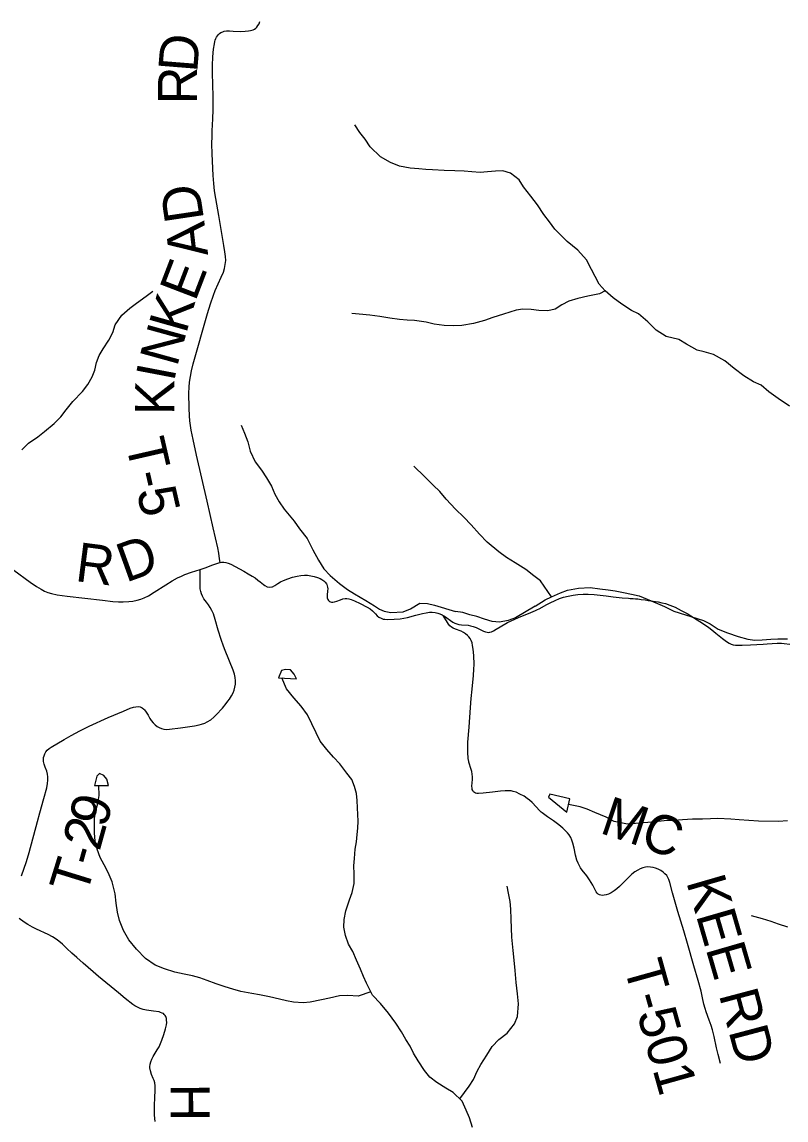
# Model space of a CAD drawing. Extents: x 0 to 34, y 0 to 22.
# Drawn here: x 7.268 to 8.379, y 17.022 to 18.618 of the extents above; entities that cross this region are included whole.
import ezdxf

# ---------------------------------------------------------------- set-up
doc = ezdxf.new("R2010")
doc.units = 0
for name, color, linetype in [('GM_X_County_Road', 7, 'Continuous'), ('GM_X_County_Road_Text', 7, 'Continuous'), ('GM_X_Minor_Lake', 7, 'Continuous'), ('GM_X_Minor_River', 7, 'Continuous'), ('GM_X_Township_Road', 7, 'Continuous'), ('GM_X_Township_Road_Text', 7, 'Continuous')]:
    doc.layers.add(name, color=color, linetype=linetype)

msp = doc.modelspace()

# ---------------------------------------------------------------- linework, layer by layer
at = {"layer": 'GM_X_County_Road'}
for points in [[(7.5272, 17.8224), (7.5359, 17.8253), (7.5444, 17.8284), (7.5514, 17.8311), (7.5545, 17.832), (7.5563, 17.8323)], [(7.5563, 17.8323), (7.5583, 17.8326), (7.5616, 17.8326), (7.5648, 17.8322), (7.5679, 17.8314), (7.572, 17.8297), (7.5781, 17.8265), (7.5906, 17.8196), (7.5971, 17.816), (7.6031, 17.8127), (7.6073, 17.8099), (7.6113, 17.8069), (7.6147, 17.8041), (7.6195, 17.8002), (7.6214, 17.7988), (7.6246, 17.7972), (7.628, 17.7965), (7.6313, 17.797), (7.6323, 17.7972), (7.6361, 17.7991), (7.6402, 17.8018), (7.644, 17.8041), (7.6485, 17.8063), (7.6549, 17.8088), (7.6615, 17.8109), (7.6682, 17.8126), (7.6738, 17.8135), (7.6788, 17.8138), (7.6832, 17.8137), (7.6883, 17.8132), (7.6932, 17.8122), (7.6981, 17.8107), (7.7016, 17.8092), (7.7044, 17.8076), (7.7071, 17.8057), (7.7089, 17.804), (7.7108, 17.8014), (7.7115, 17.8003), (7.7126, 17.7965), (7.7128, 17.7939), (7.7126, 17.7913), (7.7117, 17.7851), (7.7118, 17.7827), (7.712, 17.781), (7.7129, 17.7784), (7.7139, 17.7771), (7.7151, 17.7759), (7.717, 17.775), (7.7181, 17.7747), (7.7203, 17.7746), (7.7226, 17.7751), (7.7259, 17.7763), (7.7312, 17.7783), (7.7349, 17.7794), (7.7381, 17.7799), (7.7407, 17.7799), (7.7432, 17.7795), (7.7469, 17.7785), (7.7516, 17.7766), (7.7601, 17.7726), (7.7701, 17.7674), (7.7744, 17.7648), (7.7778, 17.762), (7.7822, 17.7575), (7.7848, 17.7549), (7.7871, 17.753), (7.7902, 17.7512), (7.7935, 17.7501), (7.7958, 17.7498), (7.8, 17.7496), (7.8093, 17.7499), (7.8179, 17.7506), (7.8234, 17.7514), (7.8288, 17.7525), (7.8407, 17.7558), (7.8503, 17.7583), (7.8558, 17.7594), (7.8608, 17.76), (7.8645, 17.76), (7.8689, 17.7597), (7.8725, 17.7588), (7.8755, 17.7578), (7.8788, 17.7563), (7.8804, 17.7553)], [(7.2568, 17.821), (7.2804, 17.8039), (7.2896, 17.7977), (7.2964, 17.7936), (7.3013, 17.7909), (7.3063, 17.7888), (7.3116, 17.7872), (7.3194, 17.7855), (7.334, 17.7833), (7.3856, 17.7774), (7.4003, 17.7757), (7.4089, 17.7751), (7.4157, 17.775), (7.4237, 17.7756), (7.4298, 17.7763), (7.4358, 17.7775), (7.4411, 17.779), (7.4462, 17.7809), (7.4523, 17.7838), (7.4607, 17.789), (7.4773, 17.7998), (7.4869, 17.8056), (7.4945, 17.8099), (7.5001, 17.8127), (7.5052, 17.8149), (7.5146, 17.8182), (7.5272, 17.8224)], [(7.8804, 17.7553), (7.8825, 17.7541), (7.8945, 17.7457), (7.8976, 17.7441), (7.9003, 17.743), (7.9032, 17.7423), (7.9073, 17.7417), (7.9167, 17.7411), (7.9204, 17.7405), (7.9241, 17.7395), (7.9282, 17.738), (7.9333, 17.7356), (7.9393, 17.7325), (7.9421, 17.7314), (7.9444, 17.7309), (7.9467, 17.7307), (7.9484, 17.7309), (7.9506, 17.7315), (7.9534, 17.7328), (7.9576, 17.7352), (7.9633, 17.7388), (7.9741, 17.7449), (7.9791, 17.7475), (7.9836, 17.7495), (7.9899, 17.7523), (8.0077, 17.7595), (8.0144, 17.7626), (8.0173, 17.7638), (8.02, 17.7652), (8.0309, 17.7711), (8.0358, 17.7738), (8.0431, 17.7772), (8.0495, 17.7798), (8.0555, 17.7818), (8.0621, 17.7835), (8.0695, 17.7849), (8.0763, 17.7858), (8.0838, 17.7863), (8.0913, 17.7863), (8.1, 17.7859), (8.1173, 17.7837), (8.1277, 17.7825), (8.1406, 17.7812), (8.1499, 17.7803), (8.1523, 17.7801), (8.1566, 17.7798), (8.1597, 17.7794), (8.1634, 17.7793), (8.1683, 17.7786), (8.1739, 17.7781), (8.1781, 17.7772), (8.1824, 17.7767), (8.1855, 17.7763), (8.1929, 17.7751), (8.1984, 17.7739), (8.2033, 17.7726), (8.2098, 17.7703), (8.2173, 17.7672), (8.2262, 17.7628), (8.235, 17.758), (8.244, 17.7526), (8.2587, 17.7433), (8.2664, 17.7379), (8.2708, 17.7345), (8.2766, 17.7298), (8.2861, 17.7218), (8.292, 17.7174), (8.2962, 17.7149), (8.2989, 17.7137), (8.3018, 17.7129), (8.3054, 17.7123), (8.3096, 17.7121), (8.3151, 17.7122), (8.3269, 17.7127), (8.3454, 17.7138), (8.351, 17.7141), (8.3659, 17.7149), (8.3722, 17.7149), (8.3759, 17.7147), (8.384, 17.7135)]]:
    msp.add_lwpolyline(points, dxfattribs=at)
at = {"layer": 'GM_X_Minor_Lake'}
for points in [[(7.6672, 17.663), (7.6639, 17.6698), (7.6587, 17.6764), (7.6515, 17.6769), (7.6458, 17.6754), (7.6411, 17.6649)], [(7.6411, 17.6649), (7.6672, 17.663)], [(7.3943, 17.5082), (7.3917, 17.5173), (7.3876, 17.5227), (7.3812, 17.5254), (7.3774, 17.5217), (7.3738, 17.5081)], [(7.3738, 17.5081), (7.3943, 17.5082)], [(8.0647, 17.4889), (8.0356, 17.4958), (8.0337, 17.4912), (8.0599, 17.4692)], [(8.0599, 17.4692), (8.0647, 17.4889)]]:
    msp.add_lwpolyline(points, dxfattribs=at)
at = {"layer": 'GM_X_Minor_River'}
for points in [[(8.3839, 18.0594), (8.3673, 18.0706), (8.3534, 18.0806), (8.3426, 18.0902), (8.3312, 18.095), (8.3173, 18.1035), (8.3034, 18.1143), (8.2895, 18.1255), (8.273, 18.1348), (8.2598, 18.1384), (8.2496, 18.1408), (8.2341, 18.1497), (8.2228, 18.1567), (8.2047, 18.1611), (8.19, 18.17), (8.1777, 18.1823), (8.1642, 18.1939), (8.154, 18.1989), (8.1401, 18.2078), (8.1273, 18.2171), (8.116, 18.2271), (8.1071, 18.2371), (8.1011, 18.2482), (8.096, 18.2585), (8.0886, 18.2722), (8.0762, 18.2864), (8.0608, 18.2988), (8.0425, 18.3169), (8.035, 18.3276), (8.0265, 18.3383), (8.0175, 18.3521), (8.0078, 18.3647), (7.9974, 18.3785), (7.9907, 18.3885), (7.9783, 18.3985), (7.967, 18.4017), (7.9564, 18.4014), (7.945, 18.4004), (7.9343, 18.3991), (7.9222, 18.4004), (7.9112, 18.4013), (7.8972, 18.4018), (7.8821, 18.402), (7.865, 18.403), (7.8552, 18.4039), (7.8449, 18.4048), (7.8324, 18.4057), (7.8169, 18.4086), (7.8037, 18.4137), (7.7894, 18.4219), (7.7744, 18.4365), (7.767, 18.4476), (7.7592, 18.4575), (7.7521, 18.4686)], [(7.2681, 17.9962), (7.2781, 18.0059), (7.2914, 18.0152), (7.301, 18.023), (7.3152, 18.0346), (7.3248, 18.0439), (7.3325, 18.0541), (7.3425, 18.0664), (7.3563, 18.081), (7.3644, 18.0912), (7.3706, 18.1021), (7.3745, 18.1119), (7.3766, 18.1232), (7.3805, 18.1331), (7.3863, 18.1432), (7.3948, 18.1556), (7.4003, 18.1669), (7.4038, 18.1779), (7.4135, 18.1918), (7.4253, 18.2019), (7.4349, 18.2093), (7.4487, 18.2197), (7.4586, 18.2268)], [(8.116, 18.2271), (8.1077, 18.2227), (8.0906, 18.2195), (8.0761, 18.2163), (8.0632, 18.2123), (8.0529, 18.2071), (8.0433, 18.2008), (8.0327, 18.1983), (8.0194, 18.1985), (8.0084, 18.2001), (7.9963, 18.2007), (7.9864, 18.1993), (7.9681, 18.1934), (7.9525, 18.1883), (7.9407, 18.1843), (7.9244, 18.18), (7.9077, 18.1768), (7.8951, 18.1762), (7.8819, 18.1771), (7.8675, 18.1789), (7.8558, 18.1817), (7.8387, 18.1842), (7.8281, 18.1847), (7.8168, 18.1856), (7.8028, 18.1877), (7.7884, 18.1901), (7.774, 18.1919), (7.7585, 18.1936), (7.7479, 18.1941)], [(7.587, 18.032), (7.5918, 18.0202), (7.5965, 18.0076), (7.6002, 17.9943), (7.6075, 17.9787), (7.6165, 17.9664), (7.6239, 17.9553), (7.631, 17.9431), (7.6361, 17.9316), (7.6421, 17.9206), (7.6495, 17.9098), (7.6641, 17.8926), (7.6719, 17.8811), (7.6831, 17.8673), (7.6912, 17.8509), (7.6994, 17.8356), (7.7072, 17.823), (7.7162, 17.8134), (7.7297, 17.8018), (7.7413, 17.7933), (7.7515, 17.7867), (7.768, 17.777), (7.7808, 17.7693)], [(8.038, 17.7825), (8.022, 17.8055), (8.0123, 17.8128), (8.0006, 17.8221), (7.9852, 17.8318), (7.9724, 17.8395), (7.9615, 17.848), (7.9443, 17.8619), (7.9334, 17.8734), (7.9211, 17.8869), (7.9106, 17.8984), (7.8986, 17.9099), (7.8848, 17.9245), (7.8754, 17.9356), (7.8657, 17.9449), (7.8533, 17.9576), (7.838, 17.9722)], [(8.014, 17.7688), (8.0285, 17.7781), (8.038, 17.7825), (8.051, 17.7884), (8.0613, 17.7921), (8.0772, 17.7949), (8.0939, 17.7958), (8.1079, 17.7941), (8.1204, 17.7928), (8.1303, 17.7912), (8.1424, 17.7887), (8.1541, 17.7863), (8.1651, 17.7839), (8.1771, 17.7792), (8.1918, 17.7729), (8.202, 17.7686), (8.2156, 17.7616)], [(7.7808, 17.7693), (7.7881, 17.7644), (7.7949, 17.7617), (7.8043, 17.7597), (7.8225, 17.7604), (7.8331, 17.7648)], [(7.8331, 17.7648), (7.8465, 17.7733), (7.8578, 17.7728), (7.8677, 17.7704), (7.8984, 17.761)], [(8.014, 17.7688), (7.9855, 17.7518), (7.9749, 17.7481), (7.9623, 17.7457), (7.9517, 17.7466), (7.9404, 17.7498), (7.9294, 17.7537), (7.9192, 17.7565), (7.909, 17.7597), (7.8984, 17.761)], [(8.2156, 17.7616), (8.2585, 17.7482), (8.2683, 17.7431), (8.2799, 17.7354), (8.2935, 17.7299), (8.3089, 17.7247), (8.3233, 17.7207), (8.3331, 17.7194), (8.3438, 17.72), (8.3563, 17.721), (8.3665, 17.7216), (8.3806, 17.7214)], [(7.7566, 17.4463), (7.7568, 17.4565), (7.7565, 17.466), (7.7559, 17.4759), (7.7553, 17.4862), (7.7543, 17.4964), (7.7518, 17.5067), (7.7478, 17.5167), (7.7407, 17.5263), (7.7303, 17.5397), (7.7213, 17.5493), (7.7116, 17.5605), (7.7019, 17.5724), (7.6961, 17.5847), (7.6898, 17.598), (7.6835, 17.6107), (7.6739, 17.6233), (7.6634, 17.6357), (7.6526, 17.6487), (7.6459, 17.6645)], [(7.7754, 17.2083), (7.7568, 17.202), (7.7421, 17.203), (7.7296, 17.2024), (7.7155, 17.1988), (7.7037, 17.1967), (7.687, 17.1931), (7.6771, 17.1921), (7.6631, 17.1931), (7.6529, 17.1951), (7.6427, 17.1976), (7.6279, 17.2008), (7.6135, 17.2037), (7.6026, 17.2057), (7.5867, 17.2086), (7.575, 17.2122), (7.5637, 17.2154), (7.5508, 17.2198), (7.5376, 17.2246), (7.5267, 17.2285), (7.5161, 17.2313), (7.504, 17.2338), (7.4908, 17.237), (7.4757, 17.2418), (7.4621, 17.2469), (7.4482, 17.2566), (7.4348, 17.2701), (7.4236, 17.2836), (7.4158, 17.2974), (7.4104, 17.3119), (7.4075, 17.3241), (7.4054, 17.337), (7.4037, 17.3507), (7.3994, 17.3679), (7.3936, 17.3817), (7.388, 17.3928), (7.3821, 17.4035), (7.3777, 17.4157), (7.3749, 17.4279), (7.3739, 17.4389), (7.3741, 17.4503), (7.3738, 17.4606), (7.3759, 17.472), (7.3787, 17.4818), (7.3808, 17.4935), (7.3803, 17.5081)], [(8.3809, 17.4566), (8.3676, 17.456), (8.3384, 17.4565), (8.3104, 17.4584), (8.2986, 17.4593), (8.2793, 17.46), (8.2687, 17.4597), (8.2573, 17.4591), (8.2425, 17.4594), (8.2281, 17.4584), (8.216, 17.4575), (8.2057, 17.4572), (8.1928, 17.4559), (8.1776, 17.4546), (8.1655, 17.4536), (8.1484, 17.452), (8.1291, 17.4557), (8.1174, 17.4619), (8.1009, 17.469), (8.0895, 17.4737), (8.0794, 17.4773), (8.0627, 17.4805)], [(7.9232, 17.0111), (7.9185, 17.0249), (7.9141, 17.0363), (7.9082, 17.0493), (7.8951, 17.0617), (7.8842, 17.0683), (7.8711, 17.0765), (7.8609, 17.0842), (7.8535, 17.0938), (7.8442, 17.108), (7.8375, 17.1191), (7.8324, 17.1291), (7.8261, 17.1391), (7.8198, 17.1502), (7.8116, 17.1628), (7.8012, 17.1774), (7.7893, 17.1913), (7.7777, 17.2036), (7.7693, 17.2208), (7.7648, 17.2307), (7.7605, 17.2411), (7.7546, 17.2541), (7.7491, 17.2667), (7.7428, 17.2774), (7.7384, 17.29), (7.7359, 17.3022), (7.7365, 17.3132), (7.7389, 17.3261), (7.7445, 17.342), (7.748, 17.3525), (7.7513, 17.3658), (7.7511, 17.3799), (7.7509, 17.3913), (7.7514, 17.4019), (7.7527, 17.4155), (7.7544, 17.4262), (7.7557, 17.4368), (7.7566, 17.4463)], [(7.9047, 17.0527), (7.9184, 17.0709), (7.9246, 17.081), (7.9301, 17.0927), (7.9351, 17.1025), (7.9437, 17.1161), (7.9518, 17.1285), (7.9614, 17.139), (7.9733, 17.1479), (7.9841, 17.1615), (7.9885, 17.1724), (7.9899, 17.1906), (7.9886, 17.2051), (7.9865, 17.2218), (7.9849, 17.2393), (7.9836, 17.2542), (7.9823, 17.2682), (7.9803, 17.2876), (7.9797, 17.3009), (7.9792, 17.3139), (7.979, 17.3283), (7.9776, 17.3393), (7.9755, 17.3515), (7.9734, 17.3618)], [(8.3813, 17.302), (8.3677, 17.3067), (8.3571, 17.3103), (8.3443, 17.3143), (8.3285, 17.3187)]]:
    msp.add_lwpolyline(points, dxfattribs=at)
at = {"layer": 'GM_X_Township_Road'}
for points in [[(7.5563, 17.8323), (7.5556, 17.8375), (7.5544, 17.8458), (7.553, 17.8538), (7.5463, 17.8828), (7.5374, 17.9215), (7.5223, 17.9882), (7.5171, 18.0112), (7.5145, 18.0246), (7.5125, 18.0381), (7.5118, 18.0456), (7.5113, 18.0567), (7.511, 18.0785), (7.5114, 18.0872), (7.512, 18.0946), (7.5132, 18.1026), (7.5148, 18.1111), (7.5173, 18.1214), (7.5381, 18.1943), (7.5424, 18.2086), (7.5466, 18.2209), (7.5494, 18.2279), (7.558, 18.2471), (7.5611, 18.2546), (7.5627, 18.2599), (7.5639, 18.2654), (7.5645, 18.2716), (7.5642, 18.2771), (7.5634, 18.2839), (7.5619, 18.2931), (7.5545, 18.3366), (7.55, 18.3616), (7.5482, 18.3726), (7.5471, 18.3831), (7.5463, 18.3949), (7.5448, 18.4265), (7.5445, 18.4408), (7.5447, 18.4519), (7.5449, 18.4598), (7.5457, 18.4775), (7.5461, 18.4905), (7.5462, 18.5101), (7.5459, 18.5268), (7.5455, 18.5442), (7.5454, 18.5547), (7.546, 18.5676), (7.547, 18.5787), (7.5481, 18.5865), (7.5488, 18.5897), (7.5494, 18.5918), (7.5501, 18.5939), (7.5512, 18.5962), (7.5524, 18.5982), (7.5539, 18.5999), (7.5555, 18.6014), (7.5573, 18.6028), (7.5601, 18.604), (7.5625, 18.6047), (7.5655, 18.6051), (7.5698, 18.6051), (7.5753, 18.6046), (7.5859, 18.6045), (7.5927, 18.6047), (7.5976, 18.6051), (7.6006, 18.6056), (7.6042, 18.6067), (7.6064, 18.6078), (7.6084, 18.6092), (7.6098, 18.6105), (7.6114, 18.6128), (7.6129, 18.6155), (7.6143, 18.619)], [(7.2678, 17.3768), (7.275, 17.3979), (7.2791, 17.4109), (7.2912, 17.4558), (7.2946, 17.4684), (7.3002, 17.4894), (7.3044, 17.505), (7.3057, 17.5111), (7.3063, 17.516), (7.3062, 17.5209), (7.3056, 17.5246), (7.3045, 17.5288), (7.3024, 17.5346), (7.3007, 17.5393), (7.2999, 17.5429), (7.2997, 17.546), (7.2999, 17.5491), (7.3005, 17.5515), (7.3017, 17.5544), (7.3033, 17.557), (7.3052, 17.5594), (7.308, 17.5619), (7.3111, 17.564), (7.3298, 17.575), (7.3401, 17.5809), (7.3526, 17.5877), (7.366, 17.5943), (7.3937, 17.6069), (7.4159, 17.6164), (7.4257, 17.6204), (7.4304, 17.6219), (7.434, 17.6226), (7.4371, 17.6228), (7.4401, 17.6224), (7.443, 17.6212), (7.4454, 17.6193), (7.4467, 17.618), (7.449, 17.615), (7.4518, 17.6102), (7.4543, 17.6058), (7.4563, 17.6027), (7.4591, 17.5994), (7.4621, 17.5963), (7.4651, 17.594), (7.4677, 17.5924), (7.4711, 17.5909), (7.4747, 17.59), (7.4784, 17.5898), (7.4828, 17.5901), (7.4988, 17.5921), (7.5191, 17.595), (7.5258, 17.5963), (7.5294, 17.5973), (7.534, 17.599), (7.5374, 17.6006), (7.5427, 17.6038), (7.5471, 17.6073), (7.5507, 17.6108), (7.5599, 17.6205), (7.5651, 17.6274), (7.5675, 17.631), (7.5698, 17.6339), (7.5729, 17.6386), (7.5752, 17.6429), (7.5767, 17.6469), (7.5779, 17.6511), (7.5787, 17.6553), (7.5788, 17.6603), (7.5782, 17.6652), (7.5771, 17.6701), (7.5751, 17.676), (7.5639, 17.7043), (7.5615, 17.7106), (7.558, 17.7206), (7.5537, 17.7341), (7.5492, 17.7495), (7.5467, 17.7577), (7.5445, 17.7628), (7.542, 17.7671), (7.5395, 17.7707), (7.5365, 17.7746), (7.5329, 17.7797), (7.5308, 17.7834), (7.5294, 17.7869), (7.5283, 17.7904), (7.5276, 17.794), (7.5272, 17.7978), (7.5272, 17.8083), (7.5272, 17.8224)], [(8.2834, 17.1039), (8.2799, 17.1171), (8.2775, 17.1267), (8.274, 17.1431), (8.2717, 17.1528), (8.2698, 17.1593), (8.267, 17.1668), (8.2626, 17.1791), (8.2611, 17.1838), (8.2594, 17.1904), (8.2573, 17.1995), (8.2551, 17.2092), (8.2511, 17.2248), (8.2449, 17.2462), (8.2356, 17.2785), (8.2301, 17.2968), (8.2213, 17.3252), (8.2137, 17.352), (8.2098, 17.367), (8.2083, 17.3717), (8.2069, 17.3745), (8.2052, 17.3771), (8.2027, 17.3798), (8.1999, 17.3823), (8.1968, 17.3844), (8.193, 17.3864), (8.189, 17.388), (8.1854, 17.389), (8.1817, 17.3896), (8.178, 17.3897), (8.1742, 17.3893), (8.1706, 17.3885), (8.1665, 17.387), (8.1632, 17.3853), (8.159, 17.3826), (8.1546, 17.3792), (8.15, 17.375), (8.1367, 17.3611), (8.1329, 17.3578), (8.1289, 17.3549), (8.1247, 17.3523), (8.1208, 17.3504), (8.1173, 17.3491), (8.1142, 17.3485), (8.1117, 17.3483), (8.1093, 17.3486), (8.1075, 17.3491), (8.1059, 17.35), (8.1041, 17.3517), (8.1027, 17.3538), (8.0978, 17.3631), (8.093, 17.3711), (8.0891, 17.3768), (8.0825, 17.385), (8.08, 17.3885), (8.0784, 17.3912), (8.0765, 17.3951), (8.0748, 17.3998), (8.0728, 17.407), (8.0707, 17.4173), (8.0689, 17.4245), (8.0675, 17.4286), (8.0658, 17.4326), (8.0636, 17.4363), (8.0613, 17.4393), (8.0584, 17.4425), (8.0543, 17.4463), (8.0486, 17.451), (8.0406, 17.457), (8.0319, 17.4628), (8.0263, 17.4668), (8.0243, 17.4682), (8.0229, 17.4694), (8.0211, 17.4711), (8.0097, 17.4833), (8.0061, 17.4868), (8.0027, 17.4895), (7.998, 17.4925), (7.992, 17.4958), (7.9864, 17.4983), (7.9822, 17.4996), (7.9792, 17.5002), (7.9755, 17.5005), (7.9706, 17.5005), (7.9638, 17.5), (7.9521, 17.4986), (7.9386, 17.497), (7.9318, 17.4965), (7.9293, 17.4967), (7.9275, 17.4971), (7.9259, 17.498), (7.9245, 17.4992), (7.9235, 17.5007), (7.9228, 17.5024), (7.9224, 17.5043), (7.9222, 17.5074), (7.9229, 17.5167), (7.923, 17.521), (7.9226, 17.5247), (7.9219, 17.5284), (7.9201, 17.5343), (7.9187, 17.5391), (7.9178, 17.542), (7.9176, 17.5432), (7.917, 17.5475), (7.9162, 17.5568), (7.9161, 17.5623), (7.9165, 17.571), (7.9182, 17.5931), (7.9201, 17.6215), (7.921, 17.6345), (7.9225, 17.648), (7.9246, 17.6683), (7.9252, 17.6775), (7.9253, 17.6843), (7.9249, 17.6972), (7.9241, 17.7064), (7.9233, 17.7119), (7.9224, 17.7155), (7.9211, 17.719), (7.9196, 17.7217), (7.9179, 17.7242), (7.9158, 17.7264), (7.9129, 17.7287), (7.9098, 17.7307), (7.9065, 17.7323), (7.8985, 17.7353), (7.8951, 17.7368), (7.8925, 17.7385), (7.8901, 17.7405), (7.8881, 17.7428), (7.8868, 17.7449), (7.8804, 17.7553)], [(7.4612, 17.045), (7.4614, 17.0525), (7.4619, 17.0667), (7.4618, 17.0717), (7.4613, 17.0759), (7.4604, 17.0795), (7.4593, 17.0823), (7.4568, 17.088), (7.455, 17.0932), (7.4544, 17.0975), (7.4544, 17.0993), (7.4548, 17.103), (7.4557, 17.1066), (7.457, 17.1101), (7.459, 17.114), (7.4651, 17.1241), (7.4676, 17.1284), (7.4697, 17.1329), (7.4718, 17.1381), (7.4747, 17.1463), (7.4771, 17.1546), (7.4783, 17.1601), (7.4788, 17.1638), (7.4787, 17.1669), (7.4783, 17.1693), (7.4773, 17.1723), (7.4765, 17.1738), (7.4753, 17.1752), (7.4739, 17.1765), (7.4723, 17.1774), (7.47, 17.1784), (7.4676, 17.1789), (7.4596, 17.1799), (7.4492, 17.1816), (7.4444, 17.1827), (7.4403, 17.1841), (7.4363, 17.1859), (7.4326, 17.188), (7.4297, 17.19), (7.4186, 17.1984), (7.4086, 17.2067), (7.3799, 17.2304), (7.3719, 17.2374), (7.3573, 17.2498), (7.348, 17.2579), (7.3411, 17.2642), (7.3339, 17.2711), (7.3272, 17.2775), (7.322, 17.2819), (7.318, 17.2849), (7.3128, 17.2882), (7.3067, 17.2914), (7.2898, 17.2992), (7.2837, 17.3022), (7.2772, 17.306), (7.2715, 17.3097), (7.2646, 17.315)], [(7.4619, 17.0198), (7.4612, 17.029), (7.4609, 17.0358), (7.4612, 17.0432), (7.4612, 17.045)]]:
    msp.add_lwpolyline(points, dxfattribs=at)

# ---------------------------------------------------------------- texts
at = {"layer": 'GM_X_County_Road_Text'}
for s, rotation, p in [('D', 19.8229, (7.4193, 17.8028)), ('R', 352.6944, (7.3445, 17.8056))]:
    msp.add_text(s, height=0.0568, rotation=rotation, dxfattribs=at).set_placement(p)
at = {"layer": 'GM_X_Township_Road_Text'}
for s, height, rotation, p in [('D', 0.0568, 85.4015, (7.523, 18.5439)), ('R', 0.0568, 89.8478, (7.5229, 18.4984)), ('D', 0.0568, 98.4882, (7.5331, 18.3312)), ('A', 0.0568, 96.5496, (7.539, 18.2795)), ('E', 0.0568, 69.0008, (7.5201, 18.2105)), ('K', 0.0568, 74.1757, (7.5069, 18.1636)), ('N', 0.0568, 74.5275, (7.4936, 18.1155)), ('I', 0.0568, 79.1635, (7.4895, 18.0938)), ('K', 0.0568, 89.7887, (7.4896, 18.0466)), ('T-5', 0.05682, 282.9183, (7.4187, 18.0064)), ('9', 0.0568, 74.5671, (7.3904, 17.4452)), ('M', 0.0568, 341.3958, (8.1063, 17.4397)), ('C', 0.0568, 339.5276, (8.1643, 17.4202)), ('2', 0.0568, 74.4939, (7.3811, 17.4114)), ('-', 0.0568, 74.2311, (7.3747, 17.3886)), ('T', 0.0568, 72.8198, (7.3617, 17.3466)), ('KEE', 0.05682, 286.1608, (8.2333, 17.3685)), ('T-501', 0.05682, 285.6424, (8.1424, 17.246)), ('RD', 0.05682, 284.8692, (8.2807, 17.2045)), ('H', 0.0568, 270.1093, (7.4844, 17.0748))]:
    msp.add_text(s, height=height, rotation=rotation, dxfattribs=at).set_placement(p)

doc.saveas('drawing.dxf')
